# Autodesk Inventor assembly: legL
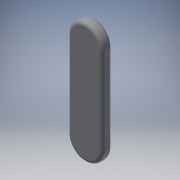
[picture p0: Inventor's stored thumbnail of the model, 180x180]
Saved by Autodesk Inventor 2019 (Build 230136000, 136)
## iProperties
Created: 2020-09
Part Number: legL
Material: 一般
Document SubType Name: Assembly
Designer: kikut
Author: kikut
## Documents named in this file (2)
- F:\openFOAM\basilisk\oversetmeshlegL\CAD\legL.iam
- F:\openFOAM\basilisk\oversetmeshlegR\CAD\leg.ipt
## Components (1 placed, 1 different names)
1. leg:1 — メイト:1, メイト:2
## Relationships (2: Mate 2)
- メイト:1 [Mate]: leg:1
- メイト:2 [Mate]: leg:1
